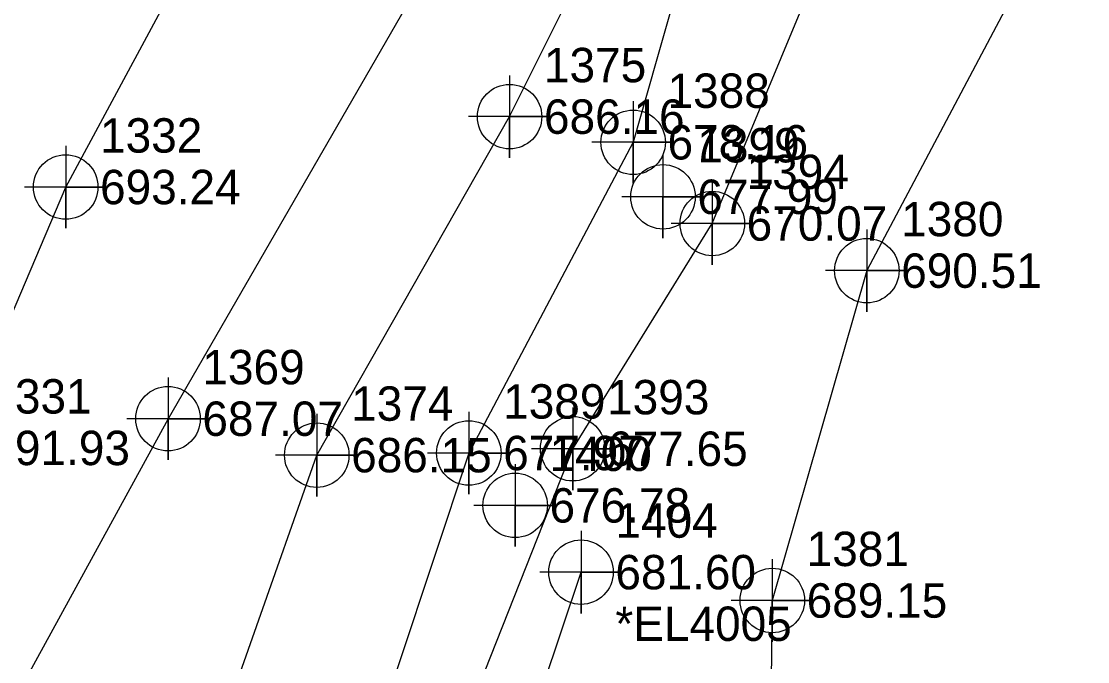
# Model space of a CAD drawing. Extents: x 1755643 to 1760494, y 736519 to 737621.
# Drawn here: x 1759066 to 1759143.6, y 737077.2 to 737123.7 of the extents above; entities that cross this region are included whole.
import ezdxf

# ---------------------------------------------------------------- set-up
doc = ezdxf.new("R2010")
doc.units = 0
for name, color, linetype in [('Exist Horizontal Alignment Direction Label', 7, 'Continuous'), ('Exist Utilities Sanitary Sewer UG Line', 7, 'Continuous'), ('Old_Level_3', 7, 'Continuous'), ('Prop Conc 5in Monolithic Keyed In Island', 7, 'Continuous'), ('Prop EOT Dash', 7, 'Continuous'), ('Prop Horizontal Alignment Station Label', 7, 'Continuous'), ('Prop Horizontal Alignment Tick Label', 7, 'Continuous'), ('Prop Horizontal Alignment Tick Large', 7, 'Continuous'), ('Prop Horizontal Alignment Tick Small', 7, 'Continuous'), ('Prop Lane Lines', 7, 'Continuous'), ('Prop Terminator CELL', 7, 'Continuous'), ('Scratch_Level_9', 7, 'Continuous')]:
    doc.layers.add(name, color=color, linetype=linetype)

msp = doc.modelspace()

# ---------------------------------------------------------------- linework, layer by layer
at = {"layer": 'Prop Horizontal Alignment Station Label'}
for points in [[(1759112.673, 737113.943), (1759112.673, 737107.943), (1759112.673, 737110.943), (1759115.673, 737110.943), (1759109.673, 737110.943)], [(1759101.92, 737091.516), (1759101.92, 737085.516), (1759101.92, 737088.516), (1759104.92, 737088.516), (1759098.92, 737088.516)]]:
    msp.add_lwpolyline(points, dxfattribs=at)
for centre in [(1759112.673, 737110.943), (1759101.92, 737088.516)]:
    msp.add_circle(centre, 2.344, dxfattribs=at)
at = {"layer": 'Prop Horizontal Alignment Tick Small'}
for points in [[(1759110.504, 737117.906), (1759110.504, 737111.906), (1759110.504, 737114.906), (1759113.504, 737114.906), (1759107.504, 737114.906)], [(1759116.257, 737112.006), (1759116.257, 737106.006), (1759116.257, 737109.006), (1759119.257, 737109.006), (1759113.257, 737109.006)], [(1759098.55, 737095.322), (1759098.55, 737089.322), (1759098.55, 737092.322), (1759101.55, 737092.322), (1759095.55, 737092.322)], [(1759106.108, 737095.633), (1759106.108, 737089.633), (1759106.108, 737092.633), (1759109.108, 737092.633), (1759103.108, 737092.633)]]:
    msp.add_lwpolyline(points, dxfattribs=at)
for centre in [(1759110.504, 737114.906), (1759116.257, 737109.006), (1759106.108, 737092.633), (1759098.55, 737092.322)]:
    msp.add_circle(centre, 2.344, dxfattribs=at)
at = {"layer": 'Prop Lane Lines'}
for points in [[(1759101.517, 737119.771), (1759101.517, 737113.771), (1759101.517, 737116.771), (1759104.517, 737116.771), (1759098.517, 737116.771)], [(1759069.232, 737114.655), (1759069.232, 737108.655), (1759069.232, 737111.655), (1759072.232, 737111.655), (1759066.232, 737111.655)], [(1759127.495, 737108.578), (1759127.495, 737102.578), (1759127.495, 737105.578), (1759130.495, 737105.578), (1759124.495, 737105.578)], [(1759076.674, 737097.816), (1759076.674, 737091.816), (1759076.674, 737094.816), (1759079.674, 737094.816), (1759073.674, 737094.816)], [(1759087.493, 737095.167), (1759087.493, 737089.167), (1759087.493, 737092.167), (1759090.493, 737092.167), (1759084.493, 737092.167)], [(1759106.711, 737086.664), (1759106.711, 737080.664), (1759106.711, 737083.664), (1759109.711, 737083.664), (1759103.711, 737083.664)], [(1759120.622, 737084.604), (1759120.622, 737078.604), (1759120.622, 737081.604), (1759123.622, 737081.604), (1759117.622, 737081.604)]]:
    msp.add_lwpolyline(points, dxfattribs=at)
for centre in [(1759101.517, 737116.771), (1759069.232, 737111.655), (1759127.495, 737105.578), (1759076.674, 737094.816), (1759087.493, 737092.167), (1759106.711, 737083.664), (1759120.622, 737081.604)]:
    msp.add_circle(centre, 2.344, dxfattribs=at)
at = {"layer": 'Prop Terminator CELL'}
for points in [[(1759091.129, 737054.232), (1759095.896, 737066.783), (1759106.108, 737092.633), (1759116.257, 737109.006), (1759126.282, 737133.12), (1759139.374, 737163.771)], [(1759129.426, 737158.51), (1759116.04, 737134.286), (1759110.504, 737114.906), (1759098.55, 737092.322), (1759085.823, 737054.025)]]:
    msp.add_lwpolyline(points, dxfattribs=at)
at = {"layer": 'Scratch_Level_9'}
for points in [[(1759028.247, 737064.277), (1759045.699, 737067.653), (1759061.181, 737092.691), (1759069.232, 737111.655), (1759085.578, 737141.979), (1759096.142, 737171.878)], [(1759114.235, 737167.89), (1759096.366, 737128.921), (1759076.674, 737094.816), (1759063.368, 737070.548), (1759053.397, 737057.897), (1759070.291, 737057.826), (1759078.132, 737065.603), (1759087.493, 737092.167), (1759101.517, 737116.771), (1759113.495, 737140.742), (1759123.733, 737160.905)], [(1759156.089, 737163.588), (1759140.962, 737130.981), (1759127.495, 737105.578), (1759120.622, 737081.604), (1759120.419, 737066.387), (1759121.445, 737059.322)], [(1759093.85, 737053.511), (1759102.509, 737071.095), (1759106.711, 737083.664)]]:
    msp.add_lwpolyline(points, dxfattribs=at)

# ---------------------------------------------------------------- texts
at = {"layer": 'Exist Horizontal Alignment Direction Label'}
msp.add_text('*EL4005', height=2.5, dxfattribs=at).set_placement((1759109.211, 737078.664))
at = {"layer": 'Exist Utilities Sanitary Sewer UG Line'}
for s, p in [('678.16', (1759113.004, 737113.656)), ('670.07', (1759118.757, 737107.756)), ('677.97', (1759101.05, 737091.072)), ('677.65', (1759108.608, 737091.383))]:
    msp.add_text(s, height=2.5, dxfattribs=at).set_placement(p)
at = {"layer": 'Old_Level_3'}
for s, p in [('686.16', (1759104.017, 737115.521)), ('693.24', (1759071.732, 737110.405)), ('690.51', (1759129.995, 737104.328)), ('687.07', (1759079.174, 737093.566)), ('691.93', (1759063.681, 737091.441)), ('686.15', (1759089.993, 737090.917)), ('681.60', (1759109.211, 737082.414)), ('689.15', (1759123.122, 737080.354))]:
    msp.add_text(s, height=2.5, dxfattribs=at).set_placement(p)
at = {"layer": 'Prop Conc 5in Monolithic Keyed In Island'}
for s, p in [('1388', (1759113.004, 737117.406)), ('1394', (1759118.757, 737111.506)), ('1389', (1759101.05, 737094.822)), ('1393', (1759108.608, 737095.133))]:
    msp.add_text(s, height=2.5, dxfattribs=at).set_placement(p)
at = {"layer": 'Prop EOT Dash'}
for s, p in [('1375', (1759104.017, 737119.271)), ('1332', (1759071.732, 737114.155)), ('1380', (1759129.995, 737108.078)), ('1369', (1759079.174, 737097.316)), ('1331', (1759063.681, 737095.191)), ('1374', (1759089.993, 737094.667)), ('1404', (1759109.211, 737086.164)), ('1381', (1759123.122, 737084.104))]:
    msp.add_text(s, height=2.5, dxfattribs=at).set_placement(p)
at = {"layer": 'Prop Horizontal Alignment Tick Label'}
for s, p in [('1399', (1759115.173, 737113.443)), ('1400', (1759104.42, 737091.016))]:
    msp.add_text(s, height=2.5, dxfattribs=at).set_placement(p)
at = {"layer": 'Prop Horizontal Alignment Tick Large'}
for s, p in [('677.99', (1759115.173, 737109.693)), ('676.78', (1759104.42, 737087.266))]:
    msp.add_text(s, height=2.5, dxfattribs=at).set_placement(p)

doc.saveas('drawing.dxf')
